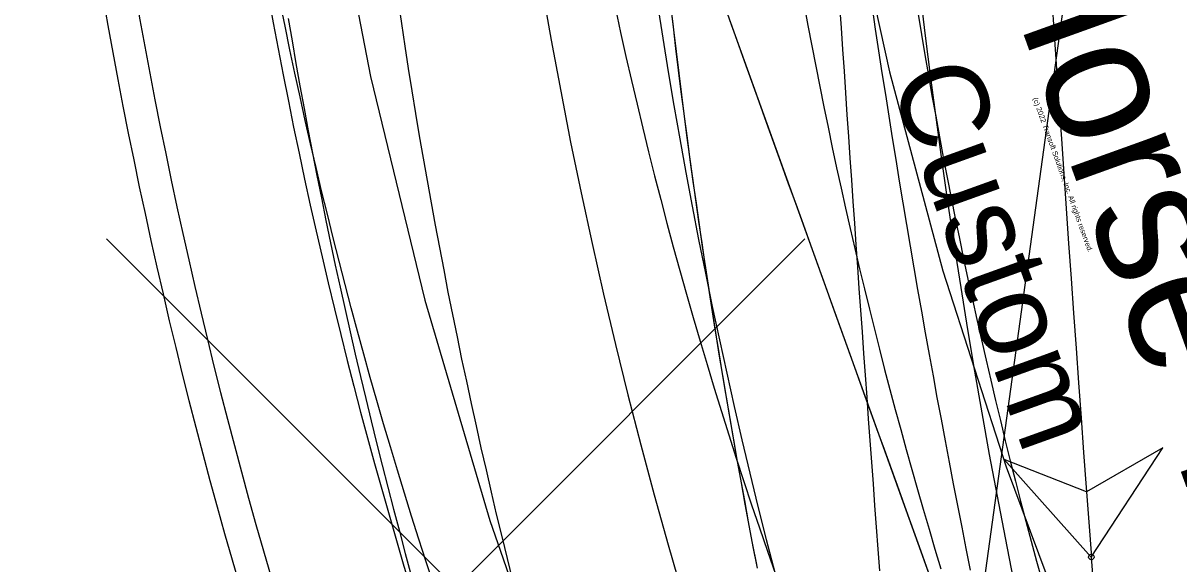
# Model space of a CAD drawing. Extents: x -14 to 1565148, y -25 to 642856.
# Drawn here: x 1564752.49 to 1564770.18, y 636462.29 to 636470.57 of the extents above; entities that cross this region are included whole.
import ezdxf

# ---------------------------------------------------------------- set-up
doc = ezdxf.new("R2010")
doc.units = 0
for name, color, linetype in [('CM_Corridor_Conceptual', 7, 'Continuous'), ('DR_P_Headwall', 7, 'Continuous'), ('GE_P_Alignment_1000_Stations', 7, 'Continuous'), ('GE_P_Alignment_100_Stations', 7, 'Continuous'), ('PV_P_EOP', 7, 'Continuous'), ('PV_X_EOP', 7, 'Continuous'), ('TR_Turning_Path22', 7, 'Continuous'), ('TR_Turning_Path28', 7, 'Continuous'), ('TR_Turning_Path28 - Copy-1', 7, 'Continuous')]:
    doc.layers.add(name, color=color, linetype=linetype)

msp = doc.modelspace()

# ---------------------------------------------------------------- linework, layer by layer
at = {"layer": 'CM_Corridor_Conceptual'}
msp.add_line((1564758.676, 636483.468), (1564770.864, 636449.594), dxfattribs=at)
msp.add_lwpolyline([(1564763.3, 636470.617), (1564763.413, 636470.304), (1564763.525, 636469.991), (1564763.638, 636469.678), (1564763.75, 636469.365), (1564763.863, 636469.052), (1564763.976, 636468.74), (1564764.088, 636468.427), (1564764.201, 636468.114), (1564764.314, 636467.801), (1564764.426, 636467.488), (1564764.539, 636467.175), (1564764.652, 636466.862), (1564764.764, 636466.549), (1564764.877, 636466.236), (1564764.99, 636465.924), (1564765.102, 636465.611), (1564765.215, 636465.298), (1564765.328, 636464.985), (1564765.441, 636464.672), (1564765.553, 636464.359), (1564765.666, 636464.046), (1564765.779, 636463.733), (1564765.892, 636463.421), (1564766.005, 636463.108), (1564766.117, 636462.795), (1564766.23, 636462.482), (1564766.343, 636462.169)], dxfattribs=at)
at = {"layer": 'DR_P_Headwall'}
for points in [[(1564763.717, 636462.277), (1564763.654, 636462.604), (1564763.593, 636462.931), (1564763.533, 636463.258), (1564763.473, 636463.586), (1564763.415, 636463.913), (1564763.357, 636464.241), (1564763.301, 636464.569), (1564763.245, 636464.897), (1564763.19, 636465.226), (1564763.136, 636465.554), (1564763.083, 636465.883), (1564763.031, 636466.212), (1564762.98, 636466.541), (1564762.93, 636466.871), (1564762.881, 636467.201), (1564762.833, 636467.531), (1564762.786, 636467.861), (1564762.739, 636468.192), (1564762.694, 636468.522), (1564762.649, 636468.853), (1564762.606, 636469.185), (1564762.563, 636469.516), (1564762.522, 636469.848), (1564762.481, 636470.18), (1564762.441, 636470.512), (1564762.403, 636470.845)], [(1564763.728, 636462.221), (1564763.665, 636462.548), (1564763.604, 636462.875), (1564763.543, 636463.202), (1564763.483, 636463.53), (1564763.425, 636463.858), (1564763.367, 636464.186), (1564763.31, 636464.514), (1564763.254, 636464.842), (1564763.199, 636465.171), (1564763.145, 636465.5), (1564763.092, 636465.829), (1564763.04, 636466.159), (1564762.989, 636466.488), (1564762.938, 636466.818), (1564762.889, 636467.148), (1564762.84, 636467.479), (1564762.793, 636467.809), (1564762.746, 636468.14), (1564762.701, 636468.472), (1564762.656, 636468.803), (1564762.612, 636469.135), (1564762.57, 636469.467), (1564762.528, 636469.799), (1564762.487, 636470.131), (1564762.447, 636470.464), (1564762.408, 636470.797)]]:
    msp.add_lwpolyline(points, dxfattribs=at)
msp.add_arc((1564877.338, 636484.105), 111.888, 180.39704, 201.6728, dxfattribs=at)
at = {"layer": 'GE_P_Alignment_1000_Stations'}
for p, q in [((1564753.764, 636467.264), (1564764.456, 636456.572)), ((1564764.456, 636467.264), (1564753.764, 636456.572))]:
    msp.add_line(p, q, dxfattribs=at)
at = {"layer": 'GE_P_Alignment_100_Stations'}
msp.add_line((1564772.301, 636499.036), (1564765.743, 636451.487), dxfattribs=at)
for points in [[(1564756.553, 636477.408), (1564756.629, 636476.696), (1564757.134, 636473.208), (1564757.805, 636469.75), (1564758.638, 636466.328), (1564759.633, 636462.95), (1564760.788, 636459.622), (1564762.1, 636456.353), (1564763.565, 636453.15), (1564763.876, 636452.518)], [(1564764.466, 636476.622), (1564764.545, 636476.012), (1564765.072, 636472.905), (1564765.748, 636469.823), (1564766.569, 636466.777), (1564767.534, 636463.773), (1564768.641, 636460.819), (1564769.887, 636457.921), (1564771.269, 636455.086), (1564771.561, 636454.527)], [(1564758.773, 636461.968), (1564758.658, 636462.318), (1564758.545, 636462.669), (1564758.434, 636463.02), (1564758.324, 636463.373), (1564758.216, 636463.725), (1564758.11, 636464.078), (1564758.005, 636464.432), (1564757.903, 636464.787), (1564757.802, 636465.142), (1564757.703, 636465.497), (1564757.605, 636465.853), (1564757.509, 636466.209), (1564757.415, 636466.566), (1564757.323, 636466.924), (1564757.232, 636467.281), (1564757.144, 636467.64), (1564757.057, 636467.999), (1564756.971, 636468.358), (1564756.888, 636468.717), (1564756.806, 636469.077), (1564756.726, 636469.438), (1564756.648, 636469.799), (1564756.571, 636470.16), (1564756.497, 636470.522), (1564756.424, 636470.884)]]:
    msp.add_lwpolyline(points, dxfattribs=at)
msp.add_arc((1564830.196, 636485.568), 70.216, 187.54952, 207.16349, dxfattribs=at)
at = {"layer": 'PV_P_EOP'}
for radius in [82.5, 82]:
    msp.add_arc((1564834.986, 636485.101), radius, 163.93404, 201.28998, dxfattribs=at)
at = {"layer": 'PV_X_EOP'}
msp.add_arc((1564834.986, 636485.101), 80, 163.93389, 201.28998, dxfattribs=at)
at = {"layer": 'TR_Turning_Path22'}
for points in [[(1564764.987, 636470.827), (1564765.009, 636470.495), (1564765.031, 636470.162), (1564765.054, 636469.83), (1564765.076, 636469.497), (1564765.099, 636469.165), (1564765.121, 636468.832), (1564765.144, 636468.5), (1564765.167, 636468.167), (1564765.19, 636467.835), (1564765.213, 636467.502), (1564765.236, 636467.17), (1564765.26, 636466.837), (1564765.283, 636466.505), (1564765.307, 636466.172), (1564765.33, 636465.84), (1564765.354, 636465.507), (1564765.378, 636465.175), (1564765.402, 636464.842), (1564765.426, 636464.51), (1564765.45, 636464.178), (1564765.474, 636463.845), (1564765.499, 636463.513), (1564765.523, 636463.18), (1564765.548, 636462.848), (1564765.572, 636462.516), (1564765.597, 636462.183)], [(1564765.483, 636470.805), (1564765.533, 636470.473), (1564765.584, 636470.14), (1564765.635, 636469.808), (1564765.687, 636469.475), (1564765.739, 636469.143), (1564765.792, 636468.811), (1564765.846, 636468.479), (1564765.9, 636468.147), (1564765.955, 636467.815), (1564766.01, 636467.484), (1564766.067, 636467.152), (1564766.123, 636466.821), (1564766.181, 636466.489), (1564766.239, 636466.158), (1564766.297, 636465.827), (1564766.357, 636465.496), (1564766.417, 636465.165), (1564766.477, 636464.834), (1564766.539, 636464.504), (1564766.601, 636464.173), (1564766.663, 636463.843), (1564766.726, 636463.512), (1564766.79, 636463.182), (1564766.855, 636462.852), (1564766.92, 636462.522), (1564766.986, 636462.192)], [(1564768.84, 636462.393), (1564769.936, 636464.066), (1564768.766, 636463.39), (1564767.508, 636463.885), (1564768.84, 636462.393)], [(1564768.84, 636462.393), (1564768.865, 636462.061), (1564768.893, 636461.729), (1564768.923, 636461.397), (1564768.956, 636461.065), (1564768.992, 636460.734), (1564769.03, 636460.402), (1564769.072, 636460.072), (1564769.116, 636459.741), (1564769.164, 636459.411), (1564769.214, 636459.082), (1564769.268, 636458.753), (1564769.325, 636458.425), (1564769.385, 636458.097)]]:
    msp.add_lwpolyline(points, dxfattribs=at)
msp.add_lwpolyline([(1564768.84, 636462.393), (1564769.936, 636464.066), (1564768.766, 636463.39), (1564767.508, 636463.885)], close=True, dxfattribs=at)
msp.add_circle((1564768.84, 636462.393), 0.0417, dxfattribs=at)
msp.add_circle((1564768.84, 636462.393), 0.0417, dxfattribs=at)
msp.add_arc((1565807.83, 636540.104), 1041.892, 182.395523, 184.277468, dxfattribs=at)
at = {"layer": 'TR_Turning_Path28'}
for points in [[(1564764.444, 636470.842), (1564764.502, 636470.53), (1564764.561, 636470.218), (1564764.621, 636469.906), (1564764.682, 636469.595), (1564764.745, 636469.284), (1564764.809, 636468.973), (1564764.874, 636468.663), (1564764.941, 636468.352), (1564765.009, 636468.042), (1564765.078, 636467.733), (1564765.148, 636467.423), (1564765.22, 636467.114), (1564765.293, 636466.805), (1564765.367, 636466.497), (1564765.442, 636466.188), (1564765.519, 636465.88), (1564765.597, 636465.573), (1564765.676, 636465.265), (1564765.757, 636464.959), (1564765.839, 636464.652), (1564765.922, 636464.346), (1564766.006, 636464.04), (1564766.091, 636463.734), (1564766.178, 636463.429), (1564766.266, 636463.124), (1564766.356, 636462.819), (1564766.446, 636462.515), (1564766.538, 636462.211)], [(1564756.545, 636470.639), (1564756.603, 636470.294), (1564756.663, 636469.95), (1564756.725, 636469.606), (1564756.787, 636469.262), (1564756.852, 636468.919), (1564756.917, 636468.575), (1564756.984, 636468.232), (1564757.053, 636467.89), (1564757.122, 636467.547), (1564757.194, 636467.205), (1564757.266, 636466.863), (1564757.34, 636466.522), (1564757.416, 636466.181), (1564757.492, 636465.84), (1564757.571, 636465.499), (1564757.65, 636465.159), (1564757.731, 636464.819), (1564757.814, 636464.479), (1564757.897, 636464.14), (1564757.983, 636463.801), (1564758.069, 636463.463), (1564758.157, 636463.124), (1564758.247, 636462.787), (1564758.337, 636462.449), (1564758.429, 636462.112)]]:
    msp.add_lwpolyline(points, dxfattribs=at)
msp.add_arc((1564840.393, 636484.698), 81.107, 162.2375, 235.00942, dxfattribs=at)
at = {"layer": 'TR_Turning_Path28 - Copy-1'}
for points in [[(1564758.227, 636470.903), (1564758.278, 636470.559), (1564758.33, 636470.215), (1564758.383, 636469.871), (1564758.438, 636469.528), (1564758.494, 636469.185), (1564758.552, 636468.842), (1564758.611, 636468.499), (1564758.671, 636468.156), (1564758.732, 636467.814), (1564758.795, 636467.472), (1564758.859, 636467.13), (1564758.925, 636466.788), (1564758.991, 636466.447), (1564759.06, 636466.106), (1564759.129, 636465.765), (1564759.2, 636465.424), (1564759.272, 636465.084), (1564759.345, 636464.744), (1564759.42, 636464.404), (1564759.496, 636464.065), (1564759.573, 636463.726), (1564759.652, 636463.387), (1564759.731, 636463.048), (1564759.813, 636462.71), (1564759.895, 636462.372), (1564759.979, 636462.035)], [(1564766.187, 636470.705), (1564766.238, 636470.392), (1564766.291, 636470.079), (1564766.345, 636469.766), (1564766.4, 636469.453), (1564766.457, 636469.14), (1564766.514, 636468.828), (1564766.573, 636468.516), (1564766.633, 636468.204), (1564766.694, 636467.893), (1564766.757, 636467.581), (1564766.821, 636467.27), (1564766.885, 636466.959), (1564766.951, 636466.649), (1564767.019, 636466.338), (1564767.087, 636466.028), (1564767.157, 636465.718), (1564767.228, 636465.409), (1564767.3, 636465.1), (1564767.373, 636464.791), (1564767.447, 636464.482), (1564767.523, 636464.173), (1564767.6, 636463.865), (1564767.678, 636463.557), (1564767.757, 636463.25), (1564767.837, 636462.943), (1564767.919, 636462.636), (1564768.001, 636462.329), (1564768.085, 636462.023)]]:
    msp.add_lwpolyline(points, dxfattribs=at)
msp.add_arc((1564847.314, 636483.896), 86.109, 162.1862, 206.90212, dxfattribs=at)

# ---------------------------------------------------------------- texts
at = {"layer": 'CM_Corridor_Conceptual'}
for s, height, p in [('Gooseneck Horse Trailer', 2, (1564762.478, 636485.19)), ('Custom', 1.3333, (1564765.743, 636469.715)), ('(c) 2022 Transoft Solutions, Inc. All rights reserved.', 0.08, (1564767.942, 636469.413))]:
    msp.add_text(s, height=height, rotation=289.7889, dxfattribs=at).set_placement(p)

doc.saveas('drawing.dxf')
